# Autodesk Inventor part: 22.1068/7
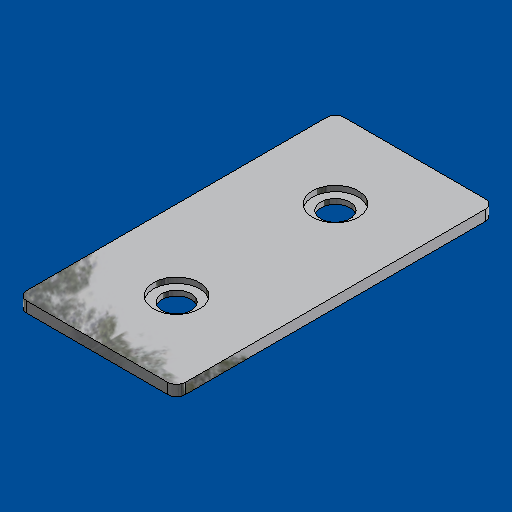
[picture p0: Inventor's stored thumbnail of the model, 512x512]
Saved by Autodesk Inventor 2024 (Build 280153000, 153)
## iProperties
Created: 2007-01
Part Number: 22.1068/7
Document SubType Name: Modeling
Designer: Andy Moles
Density: 2.7 g/cm^3
Material: Aluminum-6061
Mass: 31.2269 g
Surface Area: 88.7219 cm^2
Volume: 11.5655 cm^3
Appearance: Aluminum - Polished
Description: END CAP 45X90 AL
Stock Number: 6061 ALUMINUM
Vendor: F
FINISH: ETCH & CLEAR ANODIZE
Author: Andy Moles
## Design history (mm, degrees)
sketch "Sketch1"
  geometry: L1 (-22.5, -67.5)-(22.5, -67.5); L2 (22.5, -67.5)-(22.5, 22.5); L3 (22.5, 22.5)-(-22.5, 22.5); L4 (-22.5, 22.5)-(-22.5, -67.5); C1 r 4.1 at (0, 0); C2 r 4.1 at (0, -45); 2 further points
  constraints: 8 end point, 2 centre point, 2 parallel, 1 horizontal, 1 perpendicular, 1 vertical alignment
  dimensions: "d0" = 45 distance of L2.end L3.end; "d1" = 90 distance of L3.end L1.start; "d2" = 8.2 diameter of C1; "d15" = 22.5 distance from line of point (0, 0) L3; "d16" = 8.2 diameter of C2 (= d2); "d17" = 22.5 distance from line of L1 C2.centre (= d15); "d18" = 22.5 distance from line of C2.centre L4; "d19" = 22.5 distance from line of point (0, 0) L4 (derived)
extrude "Extrusion1" new body sketch "Sketch1" distance "d3" = 3; taper "d4" = 0 deg
fillet "Fillet1" dims "d5" = 2.5
hole "Hole1" diameter "d8" = 8.3; stored, may be unused: countersink angle "d12" = 90 deg, drill point angle "d14" = 118 deg; dims "d6" = 10, "d7" = 10, "d9" = 6, "d10" = 13, "d11" = 1.55, "d13" = 8
hole "Hole2" diameter "d22" = 8.3; stored, may be unused: countersink angle "d26" = 90 deg, drill point angle "d28" = 118 deg; dims "d20" = 10, "d21" = 10, "d23" = 6, "d24" = 13, "d25" = 1.55, "d27" = 8
body "Solid1"
